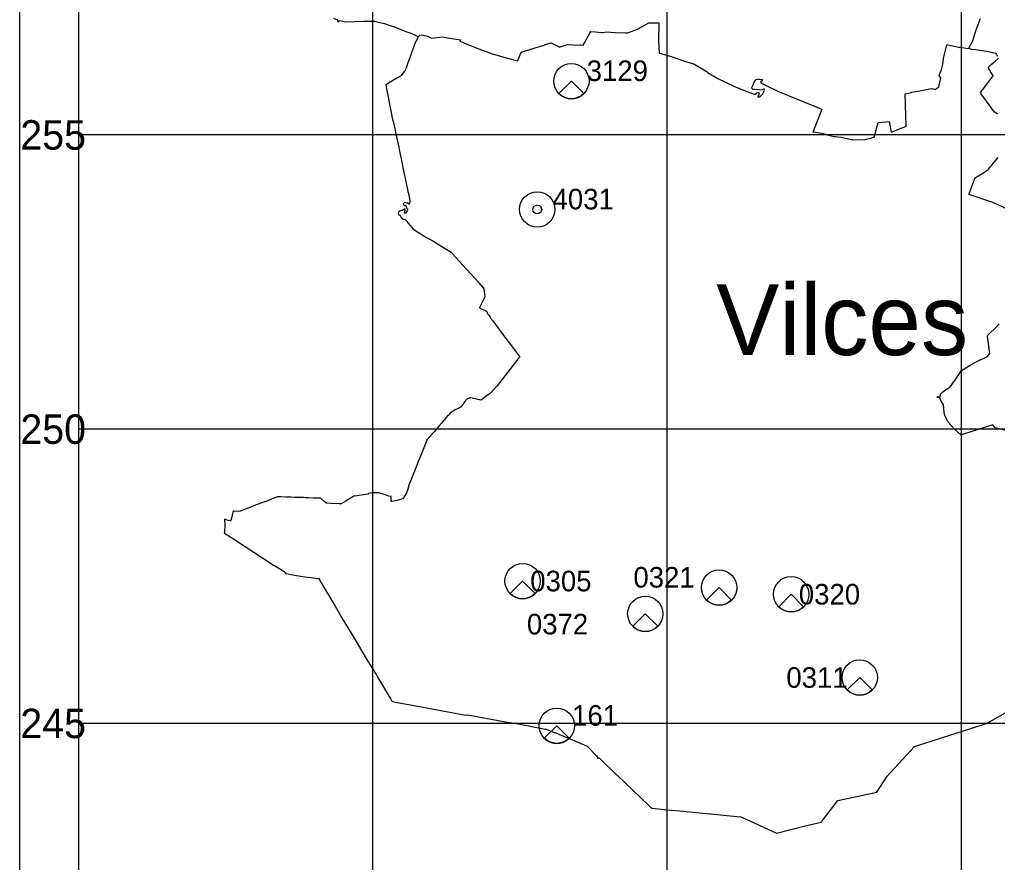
# Model space of a CAD drawing. Extents: x 459000 to 506121, y 222400 to 317452.
# Drawn here: x 459000 to 475618, y 242637 to 256960 of the extents above; entities that cross this region are included whole.
import ezdxf

# ---------------------------------------------------------------- set-up
doc = ezdxf.new("R2010")
doc.units = 0
for name, color, linetype in [('grunts_reperi', 7, 'Continuous'), ('novada_robeza', 7, 'Continuous'), ('pagastu_nosaukumi', 7, 'Continuous'), ('pagastu_robezas', 7, 'Continuous'), ('Ramis', 7, 'Continuous'), ('sienas_reperi', 7, 'Continuous'), ('valsts_robeza', 7, 'Continuous')]:
    doc.layers.add(name, color=color, linetype=linetype)

msp = doc.modelspace()

# ---------------------------------------------------------------- linework, layer by layer
at = {"layer": 'grunts_reperi'}
for radius in [300, 75]:
    msp.add_circle((467798, 253734), radius, dxfattribs=at)
at = {"layer": 'novada_robeza'}
for points in [[(465775, 256666), (465726, 256690), (465655, 256723), (465619, 256737), (465587, 256746), (465541, 256763), (465501, 256778), (465454, 256797), (465417, 256814), (465374, 256831), (465321, 256850), (465288, 256860), (465237, 256876), (465206, 256886), (465122, 256907), (465037, 256928), (464942, 256928), (464846, 256928), (464694, 256922), (464541, 256917), (464491, 256927), (464440, 256937), (464433, 256934), (464426, 256930), (464421, 256923), (464415, 256916), (464411, 256932), (464407, 256948), (464341, 256976)], [(465775, 256666), (465744, 256605), (465731, 256583), (465713, 256535), (465688, 256466), (465669, 256414), (465650, 256359), (465633, 256312), (465622, 256282), (465611, 256253), (465595, 256207), (465580, 256168), (465571, 256142), (465561, 256116), (465555, 256097), (465531, 256069), (465484, 256012), (465471, 255998), (465421, 255968), (465324, 255911), (465226, 255853), (465227, 255845), (465338, 255261), (465354, 255213), (465397, 255020), (465445, 254793), (465459, 254721), (465479, 254623), (465497, 254535), (465527, 254389), (465564, 254208), (465571, 254172), (465586, 254099), (465599, 254038), (465601, 254033), (465602, 254029), (465625, 253919), (465626, 253912), (465630, 253878), (465625, 253829), (465620, 253822), (465594, 253840), (465549, 253849), (465534, 253844), (465529, 253841), (465524, 253832), (465522, 253821), (465528, 253807), (465536, 253802), (465557, 253799), (465563, 253796), (465568, 253791), (465572, 253780), (465576, 253770), (465578, 253758), (465583, 253747), (465591, 253741), (465594, 253738), (465595, 253732), (465592, 253720), (465587, 253707), (465564, 253675), (465560, 253672), (465553, 253671), (465544, 253672), (465544, 253684), (465551, 253722), (465552, 253733), (465551, 253736), (465545, 253739), (465536, 253740), (465533, 253738), (465528, 253733), (465521, 253724), (465512, 253719), (465502, 253717), (465490, 253714), (465471, 253711), (465462, 253708), (465450, 253700), (465443, 253691), (465435, 253672), (465439, 253652), (465446, 253644), (465458, 253638), (465467, 253629), (465476, 253617), (465485, 253598), (465504, 253578), (465520, 253563), (465531, 253569), (465552, 253563), (465690, 253398), (465834, 253305), (465864, 253286), (466024, 253200), (466096, 253154), (466104, 253149), (466333, 253009), (466352, 252988), (466357, 252978), (466473, 252852), (466800, 252496), (466807, 252486), (466881, 252400), (466888, 252385), (466906, 252247), (466819, 252069), (466815, 252062), (466860, 252039), (466924, 252008), (466939, 252001), (466943, 251999), (466944, 251990), (466944, 251981), (466945, 251979), (466946, 251977), (466953, 251967), (466960, 251956), (466978, 251930), (466996, 251904), (467011, 251883), (467025, 251861), (467033, 251852), (467058, 251819), (467194, 251633), (467246, 251563), (467358, 251413), (467498, 251237), (467498, 251231), (467430, 251140), (467391, 251089), (467254, 250914), (467117, 250738), (467061, 250676), (467004, 250613), (466924, 250554), (466844, 250495), (466816, 250501), (466760, 250510), (466689, 250527), (466670, 250530), (466660, 250530), (466653, 250528), (466639, 250525), (466622, 250519), (466613, 250514), (466603, 250509), (466581, 250486), (466550, 250445), (466532, 250421), (466491, 250372), (466476, 250361), (466404, 250326), (466318, 250273), (466288, 250239), (466279, 250230), (466189, 250122), (466171, 250102), (466125, 250050), (466091, 250010), (466049, 249962), (466003, 249909), (465962, 249862), (465940, 249835), (465939, 249834), (465936, 249833), (465928, 249826), (465801, 249511), (465782, 249464), (465752, 249390), (465723, 249316), (465666, 249175), (465609, 249035), (465615, 249032), (465610, 249020), (465596, 248978), (465573, 248913), (465571, 248907), (465514, 248815), (465414, 248786), (465324, 248770), (465313, 248768), (465315, 248808), (465317, 248840), (465316, 248848), (465314, 248853), (465312, 248854), (465277, 248864), (465230, 248878), (465161, 248899), (465119, 248912), (465101, 248917), (465093, 248920), (465012, 248920), (464993, 248920), (464959, 248914), (464934, 248909), (464923, 248907), (464924, 248894), (464692, 248864), (464682, 248863), (464637, 248833), (464597, 248809), (464543, 248776), (464466, 248729), (464429, 248730), (464293, 248736), (464218, 248740), (464172, 248776), (464112, 248826), (463993, 248829), (463902, 248832), (463872, 248834), (463828, 248836), (463808, 248836), (463762, 248836), (463679, 248839), (463610, 248842), (463529, 248845), (463442, 248849), (463410, 248849), (463380, 248848), (463350, 248836), (463190, 248773), (463130, 248753), (463029, 248713), (462842, 248643), (462752, 248608), (462741, 248605), (462715, 248601), (462654, 248609), (462647, 248610), (462641, 248608), (462623, 248597), (462622, 248592), (462601, 248485), (462592, 248446), (462586, 248440), (462581, 248440), (462545, 248450), (462487, 248468), (462485, 248464), (462490, 248378), (462480, 248245), (462479, 248238)]]:
    msp.add_lwpolyline(points, dxfattribs=at)
at = {"layer": 'pagastu_robezas'}
for points in [[(475323, 256975), (475320, 256959), (475243, 256765), (475187, 256580), (475124, 256467)], [(465775, 256666), (465803, 256693), (465830, 256703), (465862, 256695), (465935, 256678), (465998, 256646), (466190, 256664), (466240, 256656), (466491, 256614), (466489, 256602), (466483, 256595), (466486, 256593), (466548, 256564), (466789, 256468), (466927, 256418), (467032, 256380), (467155, 256341), (467188, 256330), (467459, 256256), (467461, 256255), (467518, 256387), (467525, 256404), (467760, 256479), (467914, 256527), (467919, 256528), (467978, 256545), (468033, 256563), (468033, 256565), (468172, 256494), (468173, 256493), (468312, 256536), (468517, 256526), (468531, 256530), (468580, 256527), (468692, 256729), (468711, 256757), (468787, 256752), (468892, 256740), (468910, 256742), (468976, 256751), (469121, 256741), (469297, 256733), (469337, 256733), (469510, 256803), (469696, 256906), (469862, 256906), (469860, 256605), (469868, 256390), (469877, 256388), (470054, 256337), (470332, 256239), (470459, 256209), (470486, 256192), (470684, 256069), (470689, 256065), (470693, 256063), (470864, 255959), (471137, 255828), (471359, 255736), (471485, 255690), (471504, 255685), (471514, 255682), (471517, 255705), (471529, 255717), (471543, 255723), (471560, 255717), (471571, 255700), (471566, 255689), (471562, 255677), (471550, 255664), (471544, 255657), (471548, 255646), (471566, 255645), (471579, 255649), (471604, 255667), (471631, 255698), (471642, 255721), (471653, 255748), (471657, 255763), (471655, 255777), (471645, 255778), (471626, 255771), (471612, 255763), (471573, 255766), (471502, 255774), (471463, 255774), (471451, 255782), (471446, 255796), (471449, 255815), (471464, 255838), (471475, 255861), (471485, 255898), (471499, 255919), (471518, 255941), (471544, 255948), (471575, 255946), (471595, 255944), (471616, 255950), (471622, 255944), (471622, 255921), (471613, 255915), (471600, 255907), (471594, 255903), (471595, 255889), (471602, 255882), (471612, 255885), (471613, 255875), (471618, 255875), (471688, 255838), (471767, 255802), (471820, 255777), (471900, 255740), (472451, 255513), (472469, 255506), (472630, 255439), (472632, 255438), (472485, 255057), (472482, 255052), (472531, 255044), (472658, 255022), (472712, 255008), (472750, 254997), (472839, 254974), (472866, 254971), (472964, 254960), (473138, 254922), (473151, 254916), (473161, 254923), (473359, 254917), (473395, 254925), (473399, 254926), (473519, 254961), (473525, 254960), (473590, 255211), (473778, 255229), (473813, 255049), (473941, 255097), (474070, 255150), (474069, 255155), (474049, 255700), (474156, 255723), (474160, 255726), (474300, 255751), (474408, 255771), (474505, 255789), (474558, 255774), (474623, 255817), (474625, 255817), (474656, 255971), (474630, 256005), (474632, 256019), (474667, 256113), (474691, 256202), (474709, 256329), (474757, 256532), (474777, 256528), (474964, 256492), (474965, 256486), (474977, 256492), (475124, 256467)], [(475624, 256336), (475599, 256384), (475570, 256391), (475533, 256395), (475497, 256408), (475431, 256418), (475243, 256445), (475185, 256453), (475165, 256457), (475124, 256467)], [(475620, 255351), (475573, 255388), (475569, 255389), (475343, 255700), (475329, 255720), (475408, 255824), (475455, 255883), (475457, 255885), (475543, 256006), (475544, 256007), (475531, 256031), (475472, 256131), (475464, 256146), (475467, 256153), (475510, 256194), (475580, 256254), (475637, 256304)], [(475800, 253731), (475541, 253851), (475135, 253985), (475130, 253986), (475200, 254170), (475238, 254273), (475244, 254277), (475295, 254306), (475368, 254352), (475429, 254391), (475458, 254409), (475468, 254420), (475497, 254455), (475519, 254481), (475541, 254507), (475564, 254534), (475633, 254616)], [(476040, 249908), (475582, 250022), (475542, 250075), (475539, 250072), (475200, 249963), (475006, 249901), (475001, 249897), (474886, 250002), (474780, 250119), (474726, 250232), (474713, 250281), (474702, 250411), (474657, 250487), (474639, 250536), (474592, 250536), (474596, 250548), (474639, 250548), (474657, 250602), (474691, 250633), (474814, 250719), (474905, 250845), (475007, 250994), (475214, 251120), (475322, 251176), (475380, 251199), (475451, 251233), (475489, 251291), (475484, 251326), (475452, 251579), (475460, 251603), (475604, 251740), (475650, 251788)]]:
    msp.add_lwpolyline(points, dxfattribs=at)
at = {"layer": 'Ramis'}
for p, q in [((459000, 311000), (459000, 222400)), ((460000, 310000), (460000, 240000)), ((465000, 310000), (465000, 240000)), ((470000, 310000), (470000, 240000)), ((475000, 310000), (475000, 240000)), ((505000, 255000), (460000, 255000)), ((505000, 250000), (460000, 250000)), ((505000, 245000), (460000, 245000))]:
    msp.add_line(p, q, dxfattribs=at)
at = {"layer": 'sienas_reperi'}
for p, q in [((468378, 255915), (468166, 255702)), ((468590, 255702), (468378, 255915)), ((467549, 247419), (467336, 247207)), ((467761, 247207), (467549, 247419)), ((470888, 247308), (470676, 247096)), ((471101, 247096), (470888, 247308)), ((472113, 247195), (471901, 246983)), ((472325, 246983), (472113, 247195)), ((469634, 246862), (469422, 246650)), ((469846, 246650), (469634, 246862)), ((473278, 245780), (473066, 245568)), ((473490, 245568), (473278, 245780)), ((468130, 244961), (467917, 244749)), ((468342, 244749), (468130, 244961))]:
    msp.add_line(p, q, dxfattribs=at)
for centre in [(468378, 255915), (467549, 247419), (470888, 247308), (472113, 247195), (469634, 246862), (473278, 245780), (468130, 244961)]:
    msp.add_circle(centre, 300, dxfattribs=at)
for centre in [(468378, 255915), (467549, 247419), (470888, 247308), (472113, 247195), (469634, 246862), (473278, 245780), (468130, 244961)]:
    msp.add_arc(centre, 300, 225, 315, dxfattribs=at)
at = {"layer": 'valsts_robeza'}
msp.add_lwpolyline([(462479, 248238), (462483, 248235), (462634, 248137), (463328, 247684), (463335, 247683), (463498, 247581), (463510, 247570), (463517, 247558), (463522, 247547), (463562, 247539), (463618, 247530), (463707, 247515), (463856, 247492), (463954, 247478), (463995, 247471), (464027, 247466), (464042, 247464), (464060, 247464), (464080, 247468), (464235, 247210), (464239, 247201), (464330, 247047), (464364, 246994), (464502, 246755), (464616, 246564), (464740, 246361), (464799, 246258), (464927, 246045), (465007, 245918), (465024, 245892), (465046, 245856), (465048, 245852), (465107, 245750), (465282, 245456), (465302, 245423), (465326, 245375), (465353, 245365), (465766, 245290), (466520, 245149), (466554, 245143), (466595, 245140), (466616, 245145), (467224, 245034), (467508, 244986), (467931, 244904), (467948, 244900), (468086, 244847), (468094, 244844), (468636, 244618), (468639, 244617), (468650, 244608), (468804, 244447), (468817, 244431), (468825, 244405), (468837, 244418), (468843, 244417), (468853, 244410), (469147, 244128), (469156, 244120), (469438, 243851), (469542, 243751), (469542, 243751), (469723, 243578), (469740, 243563), (469742, 243562), (469745, 243562), (469755, 243559), (469802, 243553), (470006, 243534), (470006, 243533), (470284, 243507), (470443, 243494), (470494, 243487), (470733, 243462), (470743, 243461), (471190, 243418), (471258, 243412), (471475, 243316), (471486, 243311), (471863, 243135), (472330, 243251), (472620, 243322), (472758, 243500), (472907, 243692), (473567, 243834), (473742, 244102), (474210, 244606), (474670, 244754), (475165, 244913), (475444, 245002), (475756, 245177)], dxfattribs=at)

# ---------------------------------------------------------------- texts
at = {"layer": 'grunts_reperi'}
msp.add_text('  4031', height=350, dxfattribs=at).set_placement((467798, 253734))
at = {"layer": 'pagastu_nosaukumi'}
msp.add_text('Vilces', height=1200, dxfattribs=at).set_placement((470840, 251259))
at = {"layer": 'Ramis'}
for s, p in [('255', (459013, 254750)), ('250', (459014, 249750)), ('245', (459013, 244750))]:
    msp.add_text(s, height=500, dxfattribs=at).set_placement(p)
at = {"layer": 'sienas_reperi'}
for s, p in [('  3129', (468378, 255915)), ('0321  ', (469432, 247308)), (' 0305', (467549, 247244)), (' 0320', (472113, 247020)), ('0372  ', (467622, 246512)), ('0311  ', (472031, 245605)), ('  161', (468130, 244961))]:
    msp.add_text(s, height=350, dxfattribs=at).set_placement(p)

doc.saveas('drawing.dxf')
